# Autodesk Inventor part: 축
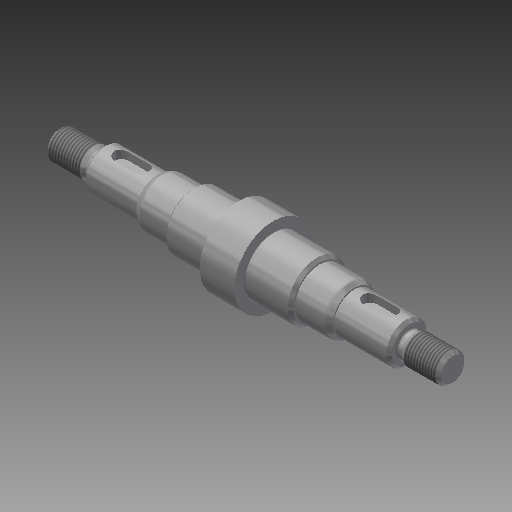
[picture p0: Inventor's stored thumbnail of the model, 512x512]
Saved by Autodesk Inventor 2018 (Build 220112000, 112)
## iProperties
Created: 2019-09
Part Number: 축
Material: 강철, 연강
Document SubType Name: Modeling
Designer: mduedu
Density: 7.86 g/cm^3
Mass: 210.278 g
Surface Area: 69.4769 cm^2
Volume: 26.7529 cm^3
Appearance: 강철
Author: mduedu
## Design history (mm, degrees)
sketch "스케치1"
  geometry: L1 (0, 0)-(15, 0); L2 (15, 0)-(15, 5); L3 (15, 5)-(0, 5); L4 (0, 5)-(0, 0); L5 (15, 0)-(34, 0); L6 (34, 0)-(34, 7); L7 (34, 7)-(15, 7); L8 (15, 7)-(15, 0); L9 (34, 0)-(46, 0); L10 (46, 0)-(46, 8.5); L11 (46, 8.5)-(34, 8.5); L12 (34, 8.5)-(34, 0); L13 (46, 0)-(62, 0); L14 (62, 10)-(46, 10); L15 (46, 10)-(46, 0); L16 (62, 10)-(62, 0); L17 (62, 0)-(68, 0); L18 (68, 0)-(68, 13.5); L19 (68, 13.5)-(62, 13.5); L20 (62, 13.5)-(62, 0)
  constraints: 40 end point, 10 parallel, 5 horizontal, 4 perpendicular, 1 vertical
  dimensions: "d2" = 15 distance of L2.end L3.end; "d3" = 19 distance of L6.end L7.end; "d8" = 16 distance of L14.start L14.end; "d9" = 10 diameter of L3 L1; "d10" = 14 diameter of L7 L5; "d11" = 17 diameter of L11 L9; "d12" = 20 diameter of L14 L13; "d73" = 12 distance of L10.end L11.end (derived); "d74" = 27 diameter of L19 L17; "d75" = 6 distance of L18.end L19.end; "d76" = 68 distance between parallel lines of L4 L18
revolve "회전1" sketch "스케치1" stored, may be unused: angle "d17" = 90 deg
revolve "회전2" stored, may be unused: angle "d22" = 90 deg
fillet "모깎기1" dims "d23" = 0.6
feature "스레드1" dims "d24" = 10, "d25" = 0
chamfer "모따기1" distance "d26" = 1; stored, may be unused: second distance "d27" = 2, angle "d28" = 45 deg
chamfer "모따기2" distance "d29" = 1; stored, may be unused: second distance "d30" = 2, angle "d31" = 45 deg
chamfer "모따기3" distance "d32" = 1.819; stored, may be unused: second distance "d33" = 2, angle "d34" = 30 deg
fillet "모깎기2" dims "d35" = 2
chamfer "모따기4" distance "d36" = 1; stored, may be unused: second distance "d37" = 2, angle "d38" = 30 deg
fillet "모깎기3" dims "d39" = 0.3
node "작업 평면1"
sketch "스케치3" dims "d51" = 12
  geometry: L1 (3, -2.5)-(-4, -2.5); L2 (-4, -2.5)-(-4, 2.5); L3 (-4, 2.5)-(3, 2.5); L4 (3, 2.5)-(3, -2.5); L5 (-9.5, 7.45)-(-9.5, -7.45) reference; 3 further points
  constraints: 8 end point, 2 midpoint, 2 parallel, 2 vertical alignment, 1 horizontal, 1 horizontal alignment, 1 perpendicular, 4 other
  dimensions: "d50" = 3 dimension on L5; "d52" = 5 distance between parallel lines of L3 L1
extrude "돌출1" cut sketch "스케치3" distance "d53" = 3; taper "d54" = 0 deg
node "솔리드1"
mirror "대칭1"
sketch "스케치2"
  geometry: L1 (0, -5)-(0, 5) reference; L2 (0, 5)-(15, 5) reference; L3 (15, 5)-(15, 7) reference; L4 (15, 7)-(34, 7) reference; L5 (34, 7)-(34, 8.5) reference; L6 (34, 8.5)-(46, 8.5) reference; L7 (46, 8.5)-(46, 10) reference; L8 (46, 10)-(62, 10) reference; L9 (62, -10)-(46, -10) reference; L10 (46, -10)-(46, -8.5) reference; L11 (46, -8.5)-(34, -8.5) reference; L12 (34, -8.5)-(34, -7) reference; L13 (34, -7)-(15, -7) reference; L14 (15, -7)-(15, -5) reference; L15 (15, -5)-(0, -5) reference; L16 (0, 0)-(74, 0); L17 (15, 5)-(12.014, 5); L18 (13.4, 4.2)-(15, 4.2); L19 (15, 4.2)-(15, 5); L20 (12.014, 5)-(13.4, 4.2); L21 (62, 10)-(62, 13.5) reference; L22 (62, 13.5)-(68, 13.5) reference; L23 (68, 13.5)-(68, -13.5) reference; L24 (68, -13.5)-(62, -13.5) reference; L25 (62, -13.5)-(62, -10) reference
  constraints: 10 end point, 1 horizontal, 1 parallel, 1 vertical
  dimensions: "d18" = 30 deg angle of L2 L20; "d19" = 8.4 diameter of L18 L16; "d21" = 2.986 distance from line of L17.end L19
node "절단 모서리 투영1"
